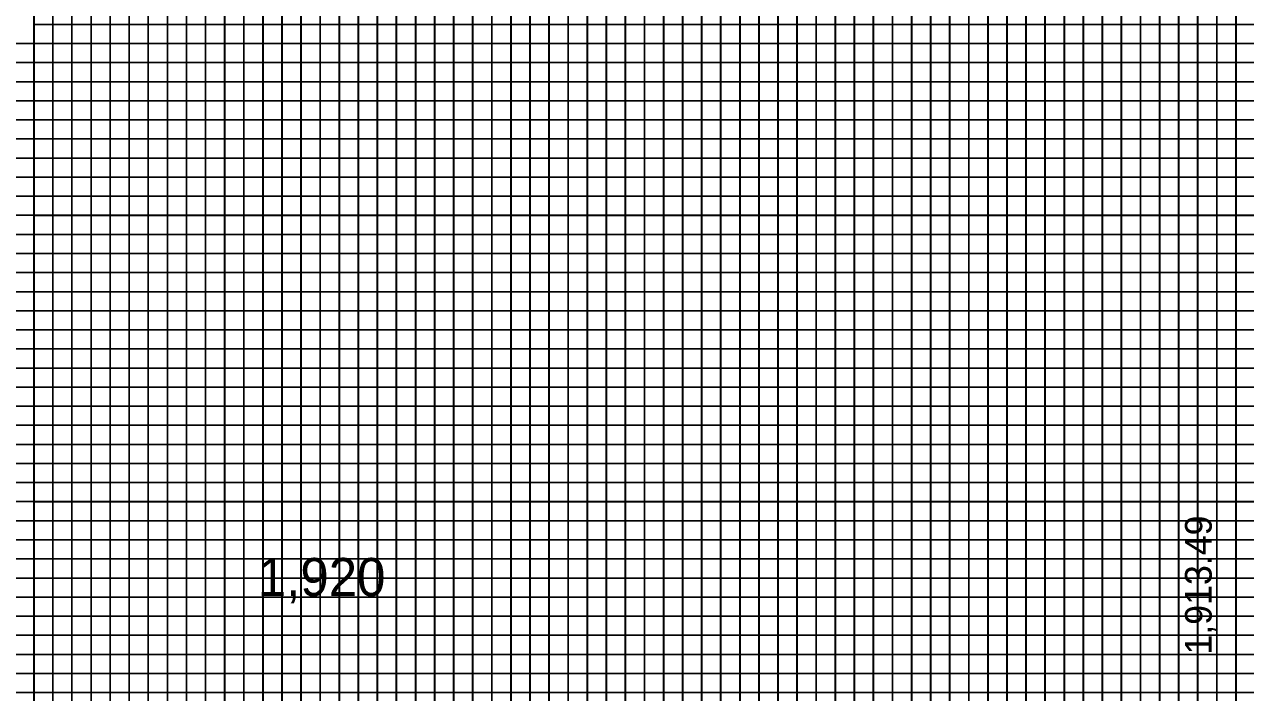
# Model space of a CAD drawing. Extents: x 553912 to 567693, y 512355 to 537539.
# Drawn here: x 566173.9 to 566493.9, y 514139.7 to 514314.7 of the extents above; entities that cross this region are included whole.
import ezdxf

# ---------------------------------------------------------------- set-up
doc = ezdxf.new("R2010")
doc.units = 0
for name, color, linetype in [('Exist Profile Cell', 7, 'Continuous'), ('Exist Vertical Profile Vertical Axis Label', 7, 'Continuous'), ('Old_Level_42', 7, 'Continuous'), ('Old_Level_53', 7, 'Continuous'), ('Old_Level_54', 7, 'Continuous'), ('Prop ROW Permanent Easement CELL', 7, 'Continuous'), ('Prop VPI Label', 7, 'Continuous'), ('Sheet DOT Grid CELL', 7, 'Continuous'), ('Sheet Profile Grid Major CELL', 7, 'Continuous'), ('Sheet Profile Grid Middle CELL', 7, 'Continuous'), ('Sheet Profile Grid Minor CELL', 7, 'Continuous'), ('Sheet Summary Guardrail CELL', 7, 'Continuous')]:
    doc.layers.add(name, color=color, linetype=linetype)

msp = doc.modelspace()

# ---------------------------------------------------------------- linework, layer by layer
at = {"layer": 'Exist Profile Cell'}
msp.add_line((566276.35, 513964.72), (566276.35, 514214.72), dxfattribs=at)
at = {"layer": 'Old_Level_42'}
for p, q in [((566226.42, 514839.71), (566226.42, 513814.71)), ((566276.42, 514839.71), (566276.42, 513814.71)), ((566326.42, 514839.71), (566326.42, 513814.71)), ((566376.42, 514839.71), (566376.42, 513814.71)), ((566426.42, 514839.71), (566426.42, 513814.71)), ((566476.42, 514839.71), (566476.42, 513814.71)), ((566176.42, 514314.71), (567676.42, 514314.71)), ((566176.42, 514264.71), (567676.42, 514264.71)), ((566176.42, 514214.71), (567676.42, 514214.71)), ((566176.42, 514164.71), (567676.42, 514164.71))]:
    msp.add_line(p, q, dxfattribs=at)
at = {"layer": 'Old_Level_53'}
msp.add_lwpolyline([(567676.42, 514839.71), (566176.42, 514839.71), (566176.42, 513789.71), (567676.42, 513789.71)], close=True, dxfattribs=at)
at = {"layer": 'Old_Level_54'}
for points in [[(566176.42, 514839.71), (566226.42, 514839.71), (566226.42, 513814.71), (566276.42, 513814.71), (566276.42, 514839.71), (566326.42, 514839.71), (566326.42, 513814.71), (566376.42, 513814.71), (566376.42, 514839.71), (566426.42, 514839.71), (566426.42, 513814.71), (566476.42, 513814.71), (566476.42, 514839.71), (566526.42, 514839.71), (566526.42, 513814.71), (566576.42, 513814.71), (566576.42, 514839.71), (566626.42, 514839.71), (566626.42, 513814.71), (566676.42, 513814.71), (566676.42, 514839.71), (566726.42, 514839.71), (566726.42, 513814.71), (566776.42, 513814.71)], [(567676.42, 514264.71), (566176.42, 514264.71), (566176.42, 514314.71), (567676.42, 514314.71)], [(567676.42, 514164.71), (566176.42, 514164.71), (566176.42, 514214.71), (567676.42, 514214.71)]]:
    msp.add_lwpolyline(points, dxfattribs=at)
at = {"layer": 'Prop ROW Permanent Easement CELL'}
for points in [[(566251.42, 513814.71), (566251.42, 514839.71), (566301.42, 514839.71), (566301.42, 513814.71), (566351.42, 513814.71), (566351.42, 514839.71), (566401.42, 514839.71), (566401.42, 513814.71), (566451.42, 513814.71), (566451.42, 514839.71), (566501.42, 514839.71), (566501.42, 513814.71), (566551.42, 513814.71), (566551.42, 514839.71), (566601.42, 514839.71), (566601.42, 513814.71), (566651.42, 513814.71), (566651.42, 514839.71), (566701.42, 514839.71), (566701.42, 513814.71), (566751.42, 513814.71), (566751.42, 514839.71), (566801.42, 514839.71)], [(567676.42, 514339.71), (566176.42, 514339.71), (566176.42, 514289.71), (567676.42, 514289.71)], [(567676.42, 514239.71), (566176.42, 514239.71), (566176.42, 514189.71), (567676.42, 514189.71)]]:
    msp.add_lwpolyline(points, dxfattribs=at)
at = {"layer": 'Sheet DOT Grid CELL'}
for p, q in [((566201.35, 513964.72), (566201.35, 514464.72)), ((566251.35, 513964.72), (566251.35, 514464.72)), ((566301.35, 513964.72), (566301.35, 514464.72)), ((566351.35, 513964.72), (566351.35, 514464.72)), ((566401.35, 513964.72), (566401.35, 514464.72)), ((566451.35, 513964.72), (566451.35, 514464.72)), ((567201.35, 514264.72), (565701.35, 514264.72)), ((567201.35, 514214.72), (565701.35, 514214.72)), ((567201.35, 514164.72), (565701.35, 514164.72))]:
    msp.add_line(p, q, dxfattribs=at)
at = {"layer": 'Sheet Profile Grid Major CELL'}
for points in [[(566001.35, 514464.72), (566051.35, 514464.72), (566051.35, 513964.72), (566101.35, 513964.72), (566101.35, 514464.72), (566151.35, 514464.72), (566151.35, 513964.72), (566201.35, 513964.72), (566201.35, 514464.72), (566251.35, 514464.72), (566251.35, 513964.72), (566301.35, 513964.72), (566301.35, 514464.72), (566351.35, 514464.72), (566351.35, 513964.72), (566401.35, 513964.72), (566401.35, 514464.72), (566451.35, 514464.72), (566451.35, 513964.72), (566501.35, 513964.72)], [(567201.35, 514264.72), (565701.35, 514264.72), (565701.35, 514214.72), (567201.35, 514214.72)], [(567201.35, 514164.72), (565701.35, 514164.72), (565701.35, 514114.72), (567201.35, 514114.72)]]:
    msp.add_lwpolyline(points, dxfattribs=at)
at = {"layer": 'Sheet Profile Grid Middle CELL'}
for points in [[(565976.35, 513964.72), (566026.35, 513964.72), (566026.35, 514464.72), (566076.35, 514464.72), (566076.35, 513964.72), (566126.35, 513964.72), (566126.35, 514464.72), (566176.35, 514464.72), (566176.35, 513964.72), (566226.35, 513964.72), (566226.35, 514464.72), (566276.35, 514464.72), (566276.35, 513964.72), (566326.35, 513964.72), (566326.35, 513964.72), (566326.35, 514464.72), (566376.35, 514464.72), (566376.35, 513964.72), (566426.35, 513964.72), (566426.35, 514464.72), (566476.35, 514464.72), (566476.35, 513964.72), (566526.35, 513964.72)], [(567201.35, 514289.72), (565701.35, 514289.72), (565701.35, 514239.72), (567026.35, 514239.72)], [(567201.35, 514189.72), (565701.35, 514189.72), (565701.35, 514139.72), (567201.35, 514139.72)]]:
    msp.add_lwpolyline(points, dxfattribs=at)
at = {"layer": 'Sheet Profile Grid Minor CELL'}
for p, q in [((565751.35, 514309.72), (567001.35, 514309.72)), ((567001.35, 514304.72), (565751.35, 514304.72)), ((565751.35, 514299.72), (567151.35, 514299.72)), ((567151.35, 514279.72), (565751.35, 514279.72)), ((565751.35, 514274.72), (567151.35, 514274.72)), ((567151.35, 514254.72), (565751.35, 514254.72)), ((565751.35, 514249.72), (567151.35, 514249.72)), ((567151.35, 514229.72), (565751.35, 514229.72)), ((565751.35, 514224.72), (567151.35, 514224.72)), ((567151.35, 514219.72), (565751.35, 514219.72)), ((565751.35, 514209.72), (567151.35, 514209.72)), ((567151.35, 514204.72), (565751.35, 514204.72)), ((565751.35, 514199.72), (567151.35, 514199.72)), ((567151.35, 514194.72), (565751.35, 514194.72)), ((565751.35, 514184.72), (567151.35, 514184.72)), ((567151.35, 514179.72), (565751.35, 514179.72)), ((565751.35, 514174.72), (567151.35, 514174.72)), ((567151.35, 514169.72), (565751.35, 514169.72)), ((565751.35, 514159.72), (567151.35, 514159.72)), ((567151.35, 514154.72), (565751.35, 514154.72)), ((565751.35, 514149.72), (567151.35, 514149.72)), ((567151.35, 514144.72), (565751.35, 514144.72))]:
    msp.add_line(p, q, dxfattribs=at)
for points in [[(566181.35, 514464.72), (566181.35, 513964.72), (566186.35, 513964.72), (566186.35, 514464.72)], [(566191.35, 514464.72), (566191.35, 513964.72), (566196.35, 513964.72), (566196.35, 514464.72)], [(566206.35, 514464.72), (566206.35, 513964.72), (566211.35, 513964.72), (566211.35, 514464.72)], [(566216.35, 514464.72), (566216.35, 513964.72), (566221.35, 513964.72), (566221.35, 514464.72)], [(566231.35, 514464.72), (566231.35, 513964.72), (566236.35, 513964.72), (566236.35, 514464.72)], [(566241.35, 514464.72), (566241.35, 513964.72), (566246.35, 513964.72), (566246.35, 514464.72)], [(566256.35, 514464.72), (566256.35, 513964.72), (566261.35, 513964.72), (566261.35, 514464.72)], [(566266.35, 514464.72), (566266.35, 513964.72), (566271.35, 513964.72), (566271.35, 514464.72)], [(566281.35, 514464.72), (566281.35, 513964.72), (566286.35, 513964.72), (566286.35, 514464.72)], [(566291.35, 514464.72), (566291.35, 513964.72), (566296.35, 513964.72), (566296.35, 514464.72)], [(566306.35, 514464.72), (566306.35, 513964.72), (566311.35, 513964.72), (566311.35, 514464.72)], [(566316.35, 514464.72), (566316.35, 513964.72), (566321.35, 513964.72), (566321.35, 514464.72)], [(566331.35, 514464.72), (566331.35, 513964.72), (566336.35, 513964.72), (566336.35, 514464.72)], [(566341.35, 514464.72), (566341.35, 513964.72), (566346.35, 513964.72), (566346.35, 514464.72)], [(566356.35, 514464.72), (566356.35, 513964.72), (566361.35, 513964.72), (566361.35, 514464.72)], [(566366.35, 514464.72), (566366.35, 513964.72), (566371.35, 513964.72), (566371.35, 514464.72)], [(566381.35, 514464.72), (566381.35, 513964.72), (566386.35, 513964.72), (566386.35, 514464.72)], [(566391.35, 514464.72), (566391.35, 513964.72), (566396.35, 513964.72), (566396.35, 514464.72)], [(566406.35, 514464.72), (566406.35, 513964.72), (566406.35, 513964.72), (566411.35, 513964.72), (566411.35, 514464.72)], [(566416.35, 514464.72), (566416.35, 513964.72), (566421.35, 513964.72), (566421.35, 514464.72)], [(566431.35, 514464.72), (566431.35, 513964.72), (566436.35, 513964.72), (566436.35, 514464.72)], [(566441.35, 514464.72), (566441.35, 513964.72), (566446.35, 513964.72), (566446.35, 514464.72)], [(566456.35, 514464.72), (566456.35, 513964.72), (566461.35, 513964.72), (566461.35, 514464.72)], [(566466.35, 514464.72), (566466.35, 513964.72), (566471.35, 513964.72), (566471.35, 514464.72)], [(566481.35, 514464.72), (566481.35, 513964.72), (566486.35, 513964.72), (566486.35, 514464.72)], [(566491.35, 514464.72), (566491.35, 513964.72), (566496.35, 513964.72)], [(567151.35, 514294.72), (565751.35, 514294.72), (565751.35, 514284.72), (567151.35, 514284.72)], [(567151.35, 514269.72), (565751.35, 514269.72), (565751.35, 514259.72), (567151.35, 514259.72)], [(567151.35, 514244.72), (565751.35, 514244.72), (565751.35, 514234.72), (567151.35, 514234.72)]]:
    msp.add_lwpolyline(points, dxfattribs=at)
at = {"layer": 'Sheet Summary Guardrail CELL'}
for points in [[(566231.42, 514839.71), (566236.42, 514839.71), (566241.42, 514839.71), (566246.42, 514839.71), (566256.42, 514839.71), (566223.37, 514839.71), (566228.37, 514839.71), (566186.42, 514839.71), (566191.42, 514839.71), (566196.42, 514839.71), (566206.42, 514839.71), (566211.42, 514839.71), (566216.42, 514839.71), (566221.42, 514839.71), (566231.42, 514839.71), (566231.42, 513814.71)], [(566236.42, 513814.71), (566236.42, 514839.71), (566241.42, 514839.71), (566241.42, 513814.71)], [(566246.42, 513814.71), (566246.42, 514839.71), (566256.42, 514839.71), (566256.42, 513814.71)], [(566261.42, 513814.71), (566261.42, 514839.71), (566266.42, 514839.71), (566266.42, 513814.71)], [(566271.42, 513814.71), (566271.42, 514839.71), (566281.42, 514839.71), (566281.42, 513814.71)], [(566286.42, 513814.71), (566286.42, 514839.71), (566291.42, 514839.71), (566291.42, 513814.71)], [(566296.42, 513814.71), (566296.42, 514839.71), (566306.42, 514839.71), (566306.42, 513814.71)], [(566311.42, 513814.71), (566311.42, 514839.71), (566316.42, 514839.71), (566316.42, 513814.71)], [(566321.42, 513814.71), (566321.42, 514839.71), (566331.42, 514839.71), (566331.42, 513814.71)], [(566336.42, 513814.71), (566336.42, 514839.71), (566341.42, 514839.71), (566341.42, 513814.71)], [(566346.42, 513814.71), (566346.42, 514839.71), (566356.42, 514839.71), (566356.42, 513814.71)], [(566361.42, 513814.71), (566361.42, 514839.71), (566366.42, 514839.71), (566366.42, 513814.71)], [(566371.42, 513814.71), (566371.42, 514839.71), (566381.42, 514839.71), (566381.42, 513814.71)], [(566386.42, 513814.71), (566386.42, 514839.71), (566391.42, 514839.71), (566391.42, 513814.71)], [(566396.42, 513814.71), (566396.42, 514839.71), (566406.42, 514839.71), (566406.42, 513814.71)], [(566411.42, 513814.71), (566411.42, 514839.71), (566416.42, 514839.71), (566416.42, 513814.71)], [(566421.42, 513814.71), (566421.42, 514839.71), (566431.42, 514839.71), (566431.42, 513814.71)], [(566436.42, 513814.71), (566436.42, 514839.71), (566436.42, 514839.71), (566441.42, 514839.71), (566441.42, 513814.71)], [(566446.42, 513814.71), (566446.42, 514839.71), (566456.42, 514839.71), (566456.42, 513814.71)], [(566461.42, 513814.71), (566461.42, 514839.71), (566466.42, 514839.71), (566466.42, 513814.71)], [(566471.42, 513814.71), (566471.42, 514839.71), (566481.42, 514839.71), (566481.42, 513814.71)], [(566486.42, 513814.71), (566486.42, 514839.71), (566491.42, 514839.71), (566491.42, 513814.71)], [(566226.42, 514309.71), (567626.42, 514309.71)], [(567626.42, 514304.71), (566226.42, 514304.71), (566226.42, 514299.71), (567626.42, 514299.71)], [(567626.42, 514294.71), (566226.42, 514294.71), (566226.42, 514284.71), (567626.42, 514284.71)], [(567626.42, 514279.71), (566226.42, 514279.71), (566226.42, 514274.71), (567626.42, 514274.71)], [(567626.42, 514269.71), (566226.42, 514269.71), (566226.42, 514259.71), (567626.42, 514259.71)], [(567626.42, 514254.71), (566226.42, 514254.71), (566226.42, 514249.71), (567626.42, 514249.71)], [(567626.42, 514244.71), (566226.42, 514244.71), (566226.42, 514234.71), (567626.42, 514234.71)], [(567626.42, 514229.71), (566226.42, 514229.71), (566226.42, 514224.71), (567626.42, 514224.71)], [(567626.42, 514219.71), (566226.42, 514219.71), (566226.42, 514209.71), (567626.42, 514209.71)], [(567626.42, 514204.71), (566226.42, 514204.71), (566226.42, 514199.71), (567626.42, 514199.71)], [(567626.42, 514194.71), (566226.42, 514194.71), (566226.42, 514184.71), (567626.42, 514184.71)], [(567626.42, 514179.71), (566226.42, 514179.71), (566226.42, 514174.71), (567626.42, 514174.71)], [(567626.42, 514169.71), (566226.42, 514169.71), (566226.42, 514159.71), (567626.42, 514159.71)], [(567626.42, 514154.71), (566226.42, 514154.71), (566226.42, 514149.71), (567626.42, 514149.71)], [(567626.42, 514144.71), (566226.42, 514144.71), (566226.42, 514134.71), (567626.42, 514134.71)]]:
    msp.add_lwpolyline(points, dxfattribs=at)

# ---------------------------------------------------------------- texts
at = {"layer": 'Exist Vertical Profile Vertical Axis Label'}
msp.add_text('1,920', height=10, dxfattribs=at).set_placement((566235.05, 514164.97))
at = {"layer": 'Prop VPI Label'}
msp.add_text('1,913.49', height=7, rotation=90, dxfattribs=at).set_placement((566485.04, 514149.66))

doc.saveas('drawing.dxf')
